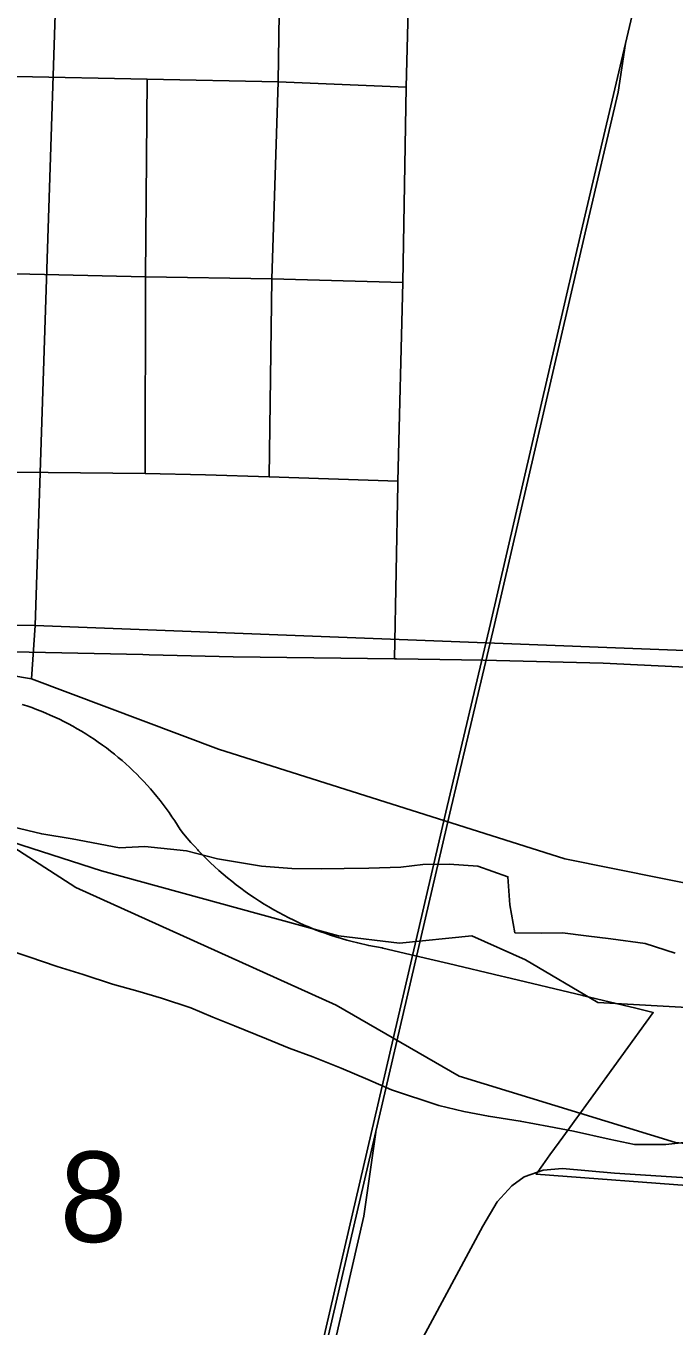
# Model space of a CAD drawing. Extents: x 0 to 34, y 0 to 22.
# Drawn here: x 5.012 to 5.312, y 16.149 to 16.751 of the extents above; entities that cross this region are included whole.
import ezdxf

# ---------------------------------------------------------------- set-up
doc = ezdxf.new("R2010")
doc.units = 0
for name, color, linetype in [('GM_X_City_Street', 7, 'Continuous'), ('GM_X_Major_River', 7, 'Continuous'), ('GM_X_Rail_Line', 7, 'Continuous'), ('GM_X_Section', 7, 'Continuous'), ('GM_X_Section_Text', 7, 'Continuous'), ('GM_X_State_Route', 7, 'Continuous'), ('GM_X_Township_Road', 7, 'Continuous'), ('SC_Shading3', 7, 'Continuous')]:
    doc.layers.add(name, color=color, linetype=linetype)

msp = doc.modelspace()

# ---------------------------------------------------------------- linework, layer by layer
at = {"layer": 'GM_X_City_Street'}
msp.add_line((4.99735, 16.46149), (5.06586, 16.46009), dxfattribs=at)
for points in [[(5.12445, 16.54233), (5.1257, 16.6339), (5.12856, 16.72514), (5.13014, 16.83042), (5.1321, 16.931)], [(5.18237, 16.45809), (5.18401, 16.53894), (5.18404, 16.54028), (5.18624, 16.63225), (5.18783, 16.72263), (5.19092, 16.84234)], [(5.00729, 16.72763), (5.06792, 16.72638), (5.12856, 16.72514), (5.18783, 16.72263)], [(5.06698, 16.54384), (5.0671, 16.63485), (5.06792, 16.72638)], [(5.00695, 16.6363), (5.0671, 16.63485), (5.1257, 16.6339), (5.18624, 16.63225)], [(5.00704, 16.5445), (5.06698, 16.54384), (5.09483, 16.54334), (5.12445, 16.54233), (5.18404, 16.54028)], [(5.06586, 16.46009), (5.06879, 16.46003), (5.10777, 16.45901), (5.18237, 16.45809), (5.18334, 16.45808)], [(5.18334, 16.45808), (5.22344, 16.45751), (5.27902, 16.45609), (5.36178, 16.45216), (5.36957, 16.45184)], [(5.24253, 16.21834), (5.25131, 16.22157), (5.26017, 16.22229), (5.28426, 16.22015), (5.34666, 16.21615), (5.41224, 16.21351), (5.43927, 16.2119), (5.44993, 16.21127), (5.49155, 16.21249), (5.52775, 16.21654), (5.56283, 16.22239), (5.62377, 16.23408), (5.67594, 16.24847), (5.71912, 16.26286), (5.78388, 16.29075), (5.80929, 16.30357), (5.83987, 16.31975), (5.88665, 16.34899), (5.91813, 16.37148), (5.93657, 16.38407), (5.95052, 16.39262), (5.95771, 16.39441), (5.96535, 16.39396), (6.021, 16.37822)], [(4.51489, 15.5535), (4.52159, 15.56417), (4.53049, 15.57454), (4.56242, 15.60678), (4.77936, 15.82003), (4.87001, 15.90938), (4.89591, 15.93654), (4.92156, 15.95891), (4.93718, 15.97172), (4.95428, 15.98373), (5.0154, 16.01925), (5.07147, 16.05155), (5.10468, 16.06989), (5.14679, 16.09095), (5.1632, 16.10078), (5.1685, 16.10607), (5.17754, 16.11537), (5.18516, 16.12558), (5.19334, 16.1399), (5.22328, 16.1956), (5.22999, 16.20684), (5.23684, 16.21421), (5.24253, 16.21834)]]:
    msp.add_lwpolyline(points, dxfattribs=at)
at = {"layer": 'GM_X_Major_River'}
for points in [[(5.20775, 16.36314), (5.1956, 16.363), (5.18534, 16.36168), (5.17053, 16.3612), (5.15914, 16.36105), (5.14852, 16.36087), (5.13487, 16.36114), (5.12085, 16.36217), (5.10043, 16.36561), (5.08609, 16.36931), (5.06677, 16.37121), (5.055, 16.37067), (5.03308, 16.3749), (5.01909, 16.37707), (5.00549, 16.38038)], [(5.31242, 16.32194), (5.29846, 16.3264), (5.28257, 16.32861), (5.27122, 16.32997), (5.26024, 16.33132), (5.25037, 16.33114), (5.23824, 16.33137), (5.23583, 16.34435), (5.23495, 16.35729), (5.22101, 16.36212), (5.20775, 16.36314)], [(5.00249, 16.32379), (5.01304, 16.32016), (5.02624, 16.31572), (5.03831, 16.31207), (5.05188, 16.30762), (5.06358, 16.30435), (5.07451, 16.3011), (5.08808, 16.29665), (5.09824, 16.29227), (5.10841, 16.28827), (5.12309, 16.28228), (5.13363, 16.27789), (5.14455, 16.27388), (5.15773, 16.26868), (5.17015, 16.2635), (5.18106, 16.25872), (5.20292, 16.25145), (5.21462, 16.24857), (5.22596, 16.24644), (5.24071, 16.24425), (5.25395, 16.24172), (5.26528, 16.23959), (5.28191, 16.23585), (5.29362, 16.23334), (5.30804, 16.23344), (5.31792, 16.23439)]]:
    msp.add_lwpolyline(points, dxfattribs=at)
at = {"layer": 'GM_X_Rail_Line'}
for points in [[(5.10395, 15.94777), (5.20624, 16.3872), (5.2269, 16.47447), (5.26889, 16.65572), (5.29316, 16.75865), (5.31038, 16.83387), (5.3257, 16.89979), (5.33706, 16.94764), (5.37114, 17.09369), (5.40174, 17.22481), (5.43081, 17.35017)], [(5.10582, 15.94734), (5.2081, 16.38677), (5.22876, 16.47404), (5.27076, 16.65529), (5.28609, 16.72031), (5.28944, 16.74286)], [(5.17374, 16.23911), (5.16824, 16.20025), (5.15468, 16.14106), (5.10782, 15.94172), (5.03795, 15.64333)]]:
    msp.add_lwpolyline(points, dxfattribs=at)
at = {"layer": 'GM_X_Section'}
for points in [[(4.04846, 17.44949), (5.04609, 17.39252), (5.01599, 16.47353), (4.01128, 16.47685)], [(5.04609, 17.39252), (6.02664, 17.37374), (6.0151, 16.4351), (5.01599, 16.47353)], [(4.01128, 16.47685), (5.01599, 16.47353), (5.01439, 16.44894), (4.95587, 16.45876), (4.90274, 16.45331), (4.8303, 16.4274), (4.76702, 16.38541), (4.66632, 16.32671), (4.58598, 16.24337), (4.51984, 16.1291), (4.42365, 16.02865), (4.33017, 15.91111), (4.26401, 15.79569), (4.21712, 15.69848), (4.13824, 15.57157), (4.05432, 15.45877), (4.01117, 15.45995)], [(5.01439, 16.44894), (5.01599, 16.47353), (6.0151, 16.4351), (6.0146, 16.38852), (5.94319, 16.37699), (5.80752, 16.37272), (5.65525, 16.35096), (5.56036, 16.3194), (5.48696, 16.32381), (5.35258, 16.34716), (5.26127, 16.36554), (5.10088, 16.41627)], [(4.93294, 16.40729), (4.97467, 16.39099), (5.03492, 16.35237), (5.15547, 16.29784), (5.21242, 16.26496), (5.31259, 16.23429), (5.43695, 16.22174), (5.56904, 16.21699), (5.70899, 16.18747), (5.84733, 16.15268), (5.92339, 16.12929), (5.9113, 16.04961), (4.91093, 16.12215)]]:
    msp.add_lwpolyline(points, close=True, dxfattribs=at)
at = {"layer": 'GM_X_State_Route'}
msp.add_lwpolyline([(5.01002, 16.43704), (5.01223, 16.43631), (5.01442, 16.43554), (5.01659, 16.43473), (5.01876, 16.43389), (5.0209, 16.433), (5.02304, 16.43208), (5.02515, 16.43112), (5.02725, 16.43013), (5.02933, 16.4291), (5.03139, 16.42803), (5.03344, 16.42693), (5.03546, 16.42579), (5.03746, 16.42462), (5.03945, 16.42341), (5.04141, 16.42216), (5.04335, 16.42089), (5.04527, 16.41958), (5.04716, 16.41823), (5.04903, 16.41686), (5.05088, 16.41545), (5.0527, 16.41401), (5.05449, 16.41253), (5.05626, 16.41103), (5.058, 16.4095), (5.05972, 16.40793), (5.06141, 16.40634), (5.06307, 16.40471), (5.0647, 16.40306), (5.0663, 16.40138), (5.06788, 16.39967), (5.06942, 16.39794), (5.07093, 16.39618), (5.07241, 16.39439), (5.07319, 16.39342), (5.07386, 16.39257), (5.07528, 16.39073), (5.07667, 16.38887), (5.07802, 16.38698), (5.07934, 16.38507), (5.08063, 16.38314), (5.08188, 16.38118), (5.0831, 16.37921), (5.08474, 16.37717), (5.08642, 16.37516), (5.0872, 16.37426), (5.08814, 16.37319), (5.08989, 16.37124), (5.09135, 16.36967), (5.09167, 16.36932), (5.09349, 16.36744), (5.09533, 16.36558), (5.09722, 16.36376), (5.09913, 16.36197), (5.10107, 16.36022), (5.10304, 16.3585), (5.10505, 16.35681), (5.10708, 16.35516), (5.10914, 16.35355), (5.11123, 16.35197), (5.11335, 16.35043), (5.11549, 16.34893), (5.11766, 16.34746), (5.11985, 16.34603), (5.12207, 16.34464), (5.12431, 16.34329), (5.12658, 16.34198), (5.12886, 16.3407), (5.13117, 16.33947), (5.13351, 16.33828), (5.13586, 16.33713), (5.13823, 16.33602), (5.14062, 16.33495), (5.14303, 16.33393), (5.14545, 16.33294), (5.1479, 16.332), (5.15035, 16.3311), (5.15283, 16.33025), (5.15532, 16.32944), (5.15782, 16.32867), (5.16033, 16.32794), (5.16286, 16.32726), (5.1654, 16.32663), (5.1705, 16.32544), (5.17668, 16.32436), (5.17697, 16.32429), (5.19217, 16.32067), (5.20737, 16.31706), (5.232, 16.3112), (5.23332, 16.31089), (5.26959, 16.30227), (5.27009, 16.30215), (5.29423, 16.29641), (5.30229, 16.29442), (5.27224, 16.25305), (5.26778, 16.24691), (5.26691, 16.24571), (5.26043, 16.23679), (5.25873, 16.23446), (5.25444, 16.22855), (5.25114, 16.22401), (5.24953, 16.22179), (5.24936, 16.22156), (5.24815, 16.2199), (5.24801, 16.2197), (5.40399, 16.20798)], dxfattribs=at)
at = {"layer": 'GM_X_Township_Road'}
for points in [[(4.99098, 16.37794), (5.04673, 16.35994), (5.15651, 16.32992), (5.18482, 16.32649), (5.21827, 16.32992), (5.24314, 16.31878), (5.27659, 16.29906), (5.37008, 16.29391), (5.46729, 16.29542), (5.48229, 16.29761), (5.48474, 16.29797), (5.48717, 16.29833), (5.4924, 16.29909), (5.53762, 16.3057), (5.63539, 16.33485), (5.70916, 16.35799), (5.76919, 16.38199), (5.81551, 16.40342), (5.89442, 16.45057), (6.00119, 16.54702)], [(6.00119, 16.54702), (5.89442, 16.45057), (5.81551, 16.40342), (5.76919, 16.38199), (5.70916, 16.35799), (5.63539, 16.33485), (5.53762, 16.3057), (5.4924, 16.29909), (5.48717, 16.29833), (5.48474, 16.29797), (5.48229, 16.29761), (5.46729, 16.29542), (5.37008, 16.29391), (5.27659, 16.29906), (5.24314, 16.31878), (5.21827, 16.32992), (5.18482, 16.32649), (5.15651, 16.32992), (5.04673, 16.35994), (4.99098, 16.37794)]]:
    msp.add_lwpolyline(points, dxfattribs=at)
at = {"layer": 'SC_Shading3'}
msp.add_lwpolyline([(5.40399, 16.20798), (5.24801, 16.2197), (5.24815, 16.2199), (5.24936, 16.22156), (5.24953, 16.22179), (5.25114, 16.22401), (5.25444, 16.22855), (5.25873, 16.23446), (5.26043, 16.23679), (5.26691, 16.24571), (5.26778, 16.24691), (5.27224, 16.25305), (5.30229, 16.29442), (5.29423, 16.29641), (5.27009, 16.30215), (5.26959, 16.30227), (5.23332, 16.31089), (5.232, 16.3112), (5.20737, 16.31706), (5.19217, 16.32067), (5.17697, 16.32429), (5.17668, 16.32436), (5.1705, 16.32544), (5.1654, 16.32663), (5.16286, 16.32726), (5.16033, 16.32794), (5.15782, 16.32867), (5.15532, 16.32944), (5.15283, 16.33025), (5.15035, 16.3311), (5.1479, 16.332), (5.14545, 16.33294), (5.14303, 16.33393), (5.14062, 16.33495), (5.13823, 16.33602), (5.13586, 16.33713), (5.13351, 16.33828), (5.13117, 16.33947), (5.12886, 16.3407), (5.12658, 16.34198), (5.12431, 16.34329), (5.12207, 16.34464), (5.11985, 16.34603), (5.11766, 16.34746), (5.11549, 16.34893), (5.11335, 16.35043), (5.11123, 16.35197), (5.10914, 16.35355), (5.10708, 16.35516), (5.10505, 16.35681), (5.10304, 16.3585), (5.10107, 16.36022), (5.09913, 16.36197), (5.09722, 16.36376), (5.09533, 16.36558), (5.09349, 16.36744), (5.09167, 16.36932), (5.09135, 16.36967), (5.08989, 16.37124), (5.08814, 16.37319), (5.0872, 16.37426), (5.08642, 16.37516), (5.08474, 16.37717), (5.0831, 16.37921), (5.08188, 16.38118), (5.08063, 16.38314), (5.07934, 16.38507), (5.07802, 16.38698), (5.07667, 16.38887), (5.07528, 16.39073), (5.07386, 16.39257), (5.07319, 16.39342), (5.07241, 16.39439), (5.07093, 16.39618), (5.06942, 16.39794), (5.06788, 16.39967), (5.0663, 16.40138), (5.0647, 16.40306), (5.06307, 16.40471), (5.06141, 16.40634), (5.05972, 16.40793), (5.058, 16.4095), (5.05626, 16.41103), (5.05449, 16.41253), (5.0527, 16.41401), (5.05088, 16.41545), (5.04903, 16.41686), (5.04716, 16.41823), (5.04527, 16.41958), (5.04335, 16.42089), (5.04141, 16.42216), (5.03945, 16.42341), (5.03746, 16.42462), (5.03546, 16.42579), (5.03344, 16.42693), (5.03139, 16.42803), (5.02933, 16.4291), (5.02725, 16.43013), (5.02515, 16.43112), (5.02304, 16.43208), (5.0209, 16.433), (5.01876, 16.43389), (5.01659, 16.43473), (5.01442, 16.43554), (5.01223, 16.43631), (5.01002, 16.43704)], dxfattribs=at)

# ---------------------------------------------------------------- texts
at = {"layer": 'GM_X_Section_Text'}
msp.add_text('8', height=0.04186, rotation=0.00001, dxfattribs=at).set_placement((5.02743, 16.18825))

doc.saveas('drawing.dxf')
